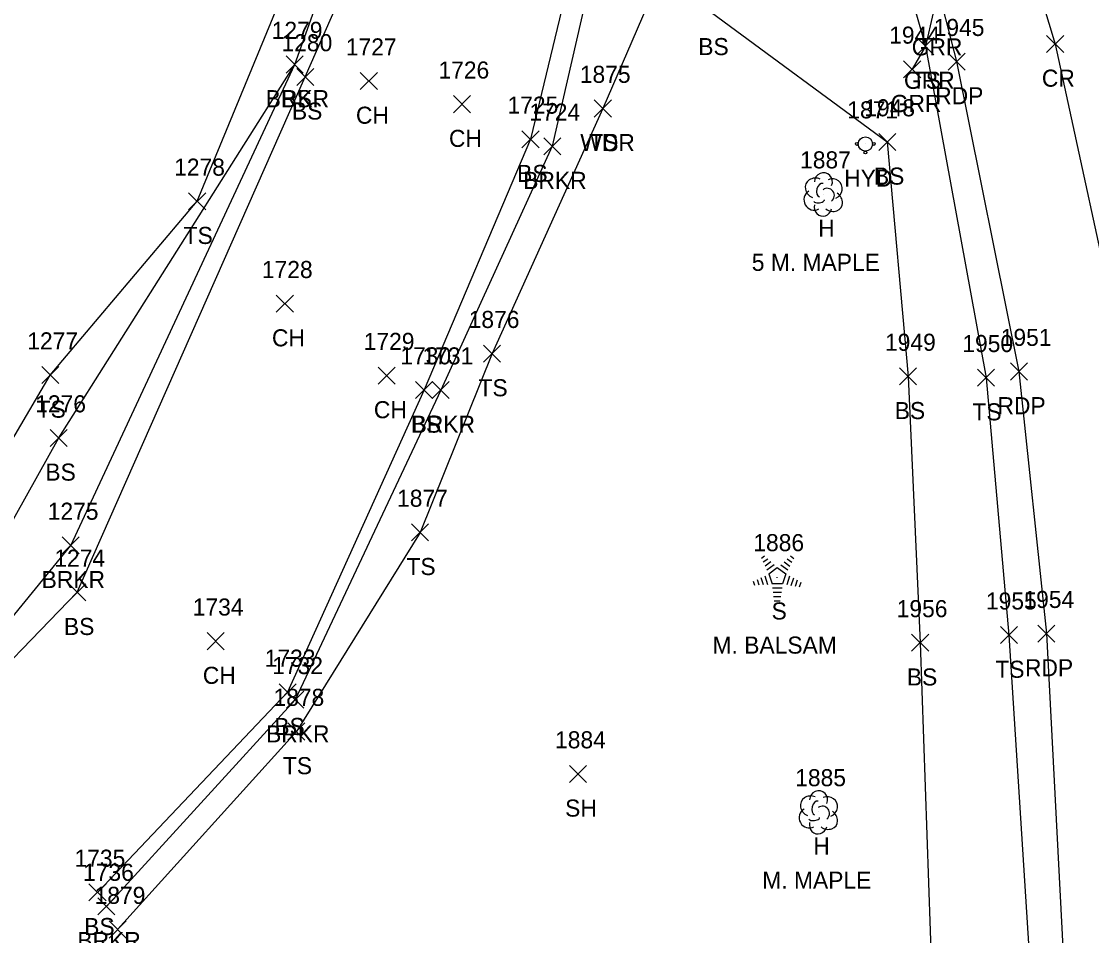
# Model space of a CAD drawing. Extents: x 1651305 to 1654558, y 539481 to 548441.
# Drawn here: x 1654251.1 to 1654376.5, y 544437.8 to 544544.9 of the extents above; entities that cross this region are included whole.
import ezdxf

# ---------------------------------------------------------------- set-up
doc = ezdxf.new("R2010")
doc.units = 0
for name, color, linetype in [('L_A', 7, 'Continuous'), ('L_C', 7, 'Continuous'), ('L_I', 7, 'Continuous'), ('L_TIC', 7, 'Continuous'), ('LAWA', 7, 'Continuous'), ('LAWE', 7, 'Continuous'), ('LELB', 7, 'Continuous'), ('LTC', 7, 'Continuous'), ('LTD', 7, 'Continuous'), ('P_A', 7, 'Continuous'), ('P_I', 7, 'Continuous'), ('P_TIC', 7, 'Continuous'), ('PET', 7, 'Continuous'), ('PRC', 7, 'Continuous'), ('R_A', 7, 'Continuous'), ('R_I', 7, 'Continuous'), ('R_TIC', 7, 'Continuous'), ('RGR', 7, 'Continuous'), ('U_A', 7, 'Continuous'), ('U_I', 7, 'Continuous'), ('UWFH', 7, 'Continuous')]:
    doc.layers.add(name, color=color, linetype=linetype)

msp = doc.modelspace()

# ---------------------------------------------------------------- linework, layer by layer
at = {"layer": 'L_TIC'}
for points in [[(1654356.01, 544541.02), (1654358.01, 544543.02)], [(1654358.01, 544541.02), (1654356.01, 544543.02)], [(1654282.12, 544538.87), (1654284.12, 544540.87)], [(1654284.12, 544538.87), (1654282.12, 544540.87)], [(1654282.12, 544538.87), (1654284.12, 544540.87)], [(1654284.12, 544538.87), (1654282.12, 544540.87)], [(1654283.35, 544537.42), (1654285.35, 544539.42)], [(1654285.35, 544537.42), (1654283.35, 544539.42)], [(1654290.8, 544536.93), (1654292.8, 544538.93)], [(1654292.8, 544536.93), (1654290.8, 544538.93)], [(1654301.71, 544534.22), (1654303.71, 544536.22)], [(1654303.71, 544534.22), (1654301.71, 544536.22)], [(1654318.22, 544533.72), (1654320.22, 544535.72)], [(1654320.22, 544533.72), (1654318.22, 544535.72)], [(1654318.22, 544533.72), (1654320.22, 544535.72)], [(1654320.22, 544533.72), (1654318.22, 544535.72)], [(1654309.74, 544530.11), (1654311.74, 544532.11)], [(1654311.74, 544530.11), (1654309.74, 544532.11)], [(1654351.54, 544529.8), (1654353.54, 544531.8)], [(1654353.54, 544529.8), (1654351.54, 544531.8)], [(1654312.3, 544529.3), (1654314.3, 544531.3)], [(1654314.3, 544529.3), (1654312.3, 544531.3)], [(1654270.69, 544522.85), (1654272.69, 544524.85)], [(1654272.69, 544522.85), (1654270.69, 544524.85)], [(1654280.96, 544510.86), (1654282.96, 544512.86)], [(1654282.96, 544510.86), (1654280.96, 544512.86)], [(1654305.24, 544505.01), (1654307.24, 544507.01)], [(1654307.24, 544505.01), (1654305.24, 544507.01)], [(1654253.47, 544502.5), (1654255.47, 544504.5)], [(1654255.47, 544502.5), (1654253.47, 544504.5)], [(1654292.9, 544502.44), (1654294.9, 544504.44)], [(1654294.9, 544502.44), (1654292.9, 544504.44)], [(1654353.98, 544502.34), (1654355.98, 544504.34)], [(1654355.98, 544502.34), (1654353.98, 544504.34)], [(1654363.12, 544502.19), (1654365.12, 544504.19)], [(1654365.12, 544502.19), (1654363.12, 544504.19)], [(1654297.27, 544500.75), (1654299.27, 544502.75)], [(1654299.27, 544500.75), (1654297.27, 544502.75)], [(1654299.22, 544500.74), (1654301.22, 544502.74)], [(1654301.22, 544500.74), (1654299.22, 544502.74)], [(1654254.46, 544495.13), (1654256.46, 544497.13)], [(1654256.46, 544495.13), (1654254.46, 544497.13)], [(1654296.8, 544484.07), (1654298.8, 544486.07)], [(1654298.8, 544484.07), (1654296.8, 544486.07)], [(1654255.87, 544482.55), (1654257.87, 544484.55)], [(1654257.87, 544482.55), (1654255.87, 544484.55)], [(1654256.64, 544477.05), (1654258.64, 544479.05)], [(1654258.64, 544477.05), (1654256.64, 544479.05)], [(1654272.86, 544471.33), (1654274.86, 544473.33)], [(1654274.86, 544471.33), (1654272.86, 544473.33)], [(1654355.4, 544471.14), (1654357.4, 544473.14)], [(1654357.4, 544471.14), (1654355.4, 544473.14)], [(1654365.8, 544472.04), (1654367.8, 544474.04)], [(1654367.8, 544472.04), (1654365.8, 544474.04)], [(1654281.29, 544465.34), (1654283.29, 544467.34)], [(1654283.29, 544465.34), (1654281.29, 544467.34)], [(1654282.17, 544464.47), (1654284.17, 544466.47)], [(1654284.17, 544464.47), (1654282.17, 544466.47)], [(1654282.32, 544460.75), (1654284.32, 544462.75)], [(1654284.32, 544460.75), (1654282.32, 544462.75)], [(1654315.31, 544455.78), (1654317.31, 544457.78)], [(1654317.31, 544455.78), (1654315.31, 544457.78)], [(1654259.01, 544441.91), (1654261.01, 544443.91)], [(1654261.01, 544441.91), (1654259.01, 544443.91)], [(1654260.06, 544440.26), (1654262.06, 544442.26)], [(1654262.06, 544440.26), (1654260.06, 544442.26)], [(1654261.37, 544437.56), (1654263.37, 544439.56)], [(1654263.37, 544437.56), (1654261.37, 544439.56)]]:
    msp.add_lwpolyline(points, dxfattribs=at)
at = {"layer": 'LAWA'}
msp.add_lwpolyline([(1654338.93, 544582.03), (1654337.56, 544570.74), (1654326.65, 544551.9), (1654319.22, 544534.72)], dxfattribs=at)
at = {"layer": 'LAWE'}
for points in [[(1654242.51, 544465.97), (1654256.87, 544483.55), (1654283.12, 544539.87), (1654291.83, 544564.24), (1654301.76, 544593.78), (1654310.98, 544627.69), (1654314.7, 544654.65), (1654333.85, 544703.3), (1654340.89, 544719.25), (1654343, 544745.95), (1654343.54, 544777), (1654341.26, 544814.62), (1654342.7, 544842.64), (1654342.65, 544866.8)], [(1654375.94, 544856.31), (1654377.08, 544805.55), (1654378.9, 544780.84), (1654375.25, 544758.97), (1654375.2, 544735.18), (1654374.98, 544710.3), (1654371.32, 544695.81), (1654368.77, 544679.57), (1654363.1, 544667.03), (1654358.05, 544658.63), (1654352.36, 544650.11), (1654344.9, 544634.32), (1654334.88, 544605.42), (1654326.4, 544588.83), (1654321.27, 544565.19), (1654313.3, 544530.3), (1654300.22, 544501.74), (1654283.17, 544465.47), (1654261.06, 544441.26)]]:
    msp.add_lwpolyline(points, dxfattribs=at)
at = {"layer": 'LELB'}
for points in [[(1654243.66, 544463.61), (1654257.64, 544478.05), (1654284.35, 544538.42), (1654294.46, 544561.39), (1654312.81, 544626.03), (1654318.85, 544643.27), (1654339.17, 544696.64), (1654344.53, 544715.65), (1654345.59, 544746.87), (1654345.75, 544776.72), (1654344.63, 544815.2), (1654344.44, 544841.84), (1654343.53, 544866.97)], [(1654374.34, 544855.82), (1654375.22, 544803.45), (1654375.07, 544780.81), (1654373.47, 544758.47), (1654373.91, 544734.87), (1654373.92, 544712.91), (1654369.62, 544696.27), (1654366.92, 544680.67), (1654362.17, 544668.56), (1654357.64, 544659.43), (1654350.7, 544650.57), (1654343.25, 544636.93), (1654333.62, 544607.27), (1654325.31, 544589.17), (1654319.06, 544565.66), (1654310.74, 544531.11), (1654298.27, 544501.75), (1654282.29, 544466.34), (1654260.01, 544442.91)], [(1654236.19, 544472.4), (1654254.47, 544503.5), (1654271.69, 544523.85), (1654289.21, 544566.35), (1654298.06, 544598.76)], [(1654343.58, 544585.05), (1654350.34, 544565.29), (1654357.01, 544542.02), (1654364.12, 544503.19), (1654366.8, 544473.04), (1654369.36, 544432.64), (1654369.04, 544397.45), (1654364.12, 544367.94), (1654358.93, 544342.15)], [(1654331.96, 544545.97), (1654352.54, 544530.8), (1654354.98, 544503.34), (1654356.4, 544472.14), (1654357.75, 544432.79), (1654359.2, 544399.51), (1654355.94, 544368.56), (1654354.81, 544342.89)], [(1654240.47, 544469.32), (1654255.46, 544496.13), (1654283.12, 544539.87)], [(1654319.22, 544534.72), (1654306.24, 544506.01), (1654297.8, 544485.07), (1654283.32, 544461.75), (1654262.37, 544438.56)]]:
    msp.add_lwpolyline(points, dxfattribs=at)
at = {"layer": 'LTC'}
for p, q in [((1654337.8, 544482.07), (1654338.15, 544482.33)), ((1654338.01, 544481.61), (1654338.54, 544481.99)), ((1654338.22, 544481.14), (1654338.92, 544481.65)), ((1654340.82, 544481.97), (1654341.37, 544481.57)), ((1654341.2, 544482.31), (1654341.61, 544482.01)), ((1654338.43, 544480.68), (1654339.3, 544481.31)), ((1654338.65, 544480.22), (1654339.66, 544480.96)), ((1654339.66, 544480.96), (1654340.66, 544480.23)), ((1654340.08, 544481.27), (1654340.89, 544480.68)), ((1654340.45, 544481.62), (1654341.13, 544481.12)), ((1654336.83, 544479.35), (1654336.98, 544478.89)), ((1654337.29, 544479.57), (1654337.5, 544478.92)), ((1654337.74, 544479.79), (1654338.01, 544478.95)), ((1654338.2, 544480), (1654338.53, 544478.98)), ((1654338.65, 544480.22), (1654339.04, 544479.03)), ((1654340.66, 544480.23), (1654340.27, 544479.03)), ((1654341.1, 544479.96), (1654340.76, 544478.92)), ((1654341.54, 544479.71), (1654341.25, 544478.83)), ((1654341.99, 544479.46), (1654341.75, 544478.73)), ((1654342.43, 544479.21), (1654342.24, 544478.64)), ((1654340.27, 544479.03), (1654339.04, 544479.03)), ((1654340.23, 544478.53), (1654339.09, 544478.53)), ((1654340.15, 544478.03), (1654339.16, 544478.03)), ((1654340.06, 544477.53), (1654339.23, 544477.53)), ((1654339.98, 544477.03), (1654339.3, 544477.03))]:
    msp.add_line(p, q, dxfattribs=at)
at = {"layer": 'LTD'}
for p, q in [((1654345.02, 544524.7), (1654345.02, 544524.7)), ((1654345.02, 544524.7), (1654345.02, 544524.7)), ((1654344.45, 544452.34), (1654344.45, 544452.34)), ((1654344.45, 544452.34), (1654344.45, 544452.34))]:
    msp.add_line(p, q, dxfattribs=at)
for centre in [(1654345.07, 544526.14), (1654344.5, 544453.77)]:
    msp.add_arc(centre, 1.05, 335.5272, 180.9563, dxfattribs=at)
for centre, major_axis, ratio, start_param, end_param in [((1654344.23, 544525.37), (1.21, -0.51), 0.895232, 1.570796, 4.712389), ((1654344.81, 544525.16), (-0.208, -0.792), 0.645439, 3.141593, 6.283185), ((1654346.06, 544525.29), (-1.14, -0.48), 0.949671, 1.570796, 4.712389), ((1654343.94, 544523.99), (0.58, -1.04), 0.959034, 3.141593, 6.283185), ((1654345.52, 544524.54), (-0.5, 0.667), 0.989748, 3.141593, 6.283185), ((1654346.02, 544523.87), (-1.09, 0.79), 0.841452, 1.570796, 4.712389), ((1654345.02, 544523.2), (0.26, 1.06), 0.942809, 1.570796, 4.712389), ((1654344.56, 544523.95), (-0.625, -0.083), 0.423636, 0, 3.141593), ((1654343.66, 544453), (1.21, -0.51), 0.895232, 1.570796, 4.712389), ((1654345.49, 544452.92), (-1.14, -0.48), 0.949671, 1.570796, 4.712389), ((1654344.24, 544452.79), (-0.208, -0.792), 0.645439, 3.141593, 6.283185), ((1654344.95, 544452.17), (-0.5, 0.667), 0.989748, 3.141593, 6.283185), ((1654343.37, 544451.63), (0.58, -1.04), 0.959034, 3.141593, 6.283185), ((1654343.99, 544451.59), (-0.625, -0.083), 0.423636, 0, 3.141593), ((1654345.45, 544451.5), (-1.09, 0.79), 0.841452, 1.570796, 4.712389), ((1654344.45, 544450.84), (0.26, 1.06), 0.942809, 1.570796, 4.712389)]:
    msp.add_ellipse(centre, major_axis=major_axis, ratio=ratio, start_param=start_param, end_param=end_param, dxfattribs=at)
at = {"layer": 'P_TIC'}
for points in [[(1654371.22, 544541.27), (1654373.22, 544543.27)], [(1654373.22, 544541.27), (1654371.22, 544543.27)], [(1654359.67, 544539.21), (1654361.67, 544541.21)], [(1654361.67, 544539.21), (1654359.67, 544541.21)], [(1654366.97, 544502.91), (1654368.97, 544504.91)], [(1654368.97, 544502.91), (1654366.97, 544504.91)], [(1654370.19, 544472.22), (1654372.19, 544474.22)], [(1654372.19, 544472.22), (1654370.19, 544474.22)]]:
    msp.add_lwpolyline(points, dxfattribs=at)
at = {"layer": 'PET'}
msp.add_lwpolyline([(1654345.04, 544588.36), (1654352.84, 544566.03), (1654357.71, 544551.64), (1654360.67, 544540.21), (1654367.97, 544503.91), (1654371.19, 544473.22), (1654373.31, 544432.69), (1654372.37, 544396.63), (1654369.95, 544367.4), (1654366.85, 544341.54), (1654364.49, 544322.02), (1654359.18, 544276.5), (1654356.39, 544249.38), (1654353.63, 544216.56), (1654349.27, 544178.19), (1654347.29, 544164.71), (1654345.69, 544149.48), (1654340.92, 544117.48), (1654336.05, 544077.13)], dxfattribs=at)
at = {"layer": 'PRC'}
msp.add_lwpolyline([(1654350.59, 544607.19), (1654355.93, 544592.7), (1654363.68, 544570.63), (1654372.22, 544542.27), (1654380.24, 544505.39), (1654384.95, 544473.92), (1654386.82, 544433.75), (1654385.71, 544395.52), (1654383.86, 544366), (1654380.92, 544339.65), (1654378, 544311.09), (1654373.89, 544274.84), (1654369.01, 544231.01), (1654366.63, 544212.46), (1654362.44, 544177.97), (1654359.49, 544151.89), (1654354.07, 544107.93), (1654348.42, 544063.01)], dxfattribs=at)
at = {"layer": 'R_TIC'}
for points in [[(1654356.01, 544541.02), (1654358.01, 544543.02)], [(1654358.01, 544541.02), (1654356.01, 544543.02)], [(1654354.46, 544538.31), (1654356.46, 544540.31)], [(1654356.46, 544538.31), (1654354.46, 544540.31)]]:
    msp.add_lwpolyline(points, dxfattribs=at)
at = {"layer": 'RGR'}
msp.add_lwpolyline([(1654344.61, 544587.06), (1654352.32, 544566.01), (1654357.15, 544551.7), (1654357.92, 544545.93), (1654357.01, 544542.02), (1654355.46, 544539.31)], dxfattribs=at)
at = {"layer": 'UWFH'}
msp.add_line((1654349.98, 544530.56), (1654349.98, 544530.56), dxfattribs=at)
for centre, radius in [((1654348.98, 544530.56), 0.167), ((1654349.98, 544530.56), 0.833), ((1654350.98, 544530.56), 0.167), ((1654349.98, 544529.56), 0.167)]:
    msp.add_circle(centre, radius, dxfattribs=at)

# ---------------------------------------------------------------- texts
at = {"layer": 'L_A'}
for s, p in [('BS', (1654330.4, 544540.97)), ('TS', (1654355.42, 544537.02)), ('BRKR', (1654279.71, 544534.87)), ('BS', (1654281.56, 544534.87)), ('BS', (1654282.79, 544533.42)), ('CH', (1654290.29, 544532.93)), ('CH', (1654301.19, 544530.22)), ('WDR', (1654316.58, 544529.72)), ('TS', (1654317.63, 544529.72)), ('BS', (1654309.18, 544526.11)), ('BRKR', (1654309.89, 544525.3)), ('BS', (1654350.98, 544525.8)), ('TS', (1654270.1, 544518.85)), ('H', (1654344.45, 544519.7)), ('CH', (1654280.45, 544506.86)), ('TS', (1654304.65, 544501.01)), ('TS', (1654252.88, 544498.5)), ('CH', (1654292.39, 544498.44)), ('BS', (1654353.42, 544498.34)), ('TS', (1654362.52, 544498.19)), ('BS', (1654296.71, 544496.75)), ('BRKR', (1654296.81, 544496.74)), ('BS', (1654253.9, 544491.13)), ('TS', (1654296.21, 544480.07)), ('BRKR', (1654253.46, 544478.55)), ('S', (1654338.99, 544474.87)), ('BS', (1654256.08, 544473.05)), ('CH', (1654272.35, 544467.33)), ('BS', (1654354.84, 544467.14)), ('TS', (1654365.21, 544468.04)), ('BS', (1654280.73, 544461.34)), ('BRKR', (1654279.76, 544460.47)), ('TS', (1654281.73, 544456.75)), ('SH', (1654314.8, 544451.78)), ('H', (1654343.88, 544447.34)), ('BS', (1654258.45, 544437.91)), ('BRKR', (1654257.65, 544436.26))]:
    msp.add_text(s, height=2, dxfattribs=at).set_placement(p)
at = {"layer": 'L_C'}
for s, p in [('5 M. MAPLE', (1654336.67, 544515.7)), ('M. BALSAM', (1654332.07, 544470.87)), ('M. MAPLE', (1654337.9, 544443.34))]:
    msp.add_text(s, height=2, dxfattribs=at).set_placement(p)
at = {"layer": 'L_I'}
for s, p in [('1279', (1654280.42, 544542.87)), ('1279', (1654280.42, 544542.87)), ('1280', (1654281.57, 544541.42)), ('1727', (1654289.11, 544540.93)), ('1726', (1654299.96, 544538.22)), ('1875', (1654316.52, 544537.72)), ('1875', (1654316.52, 544537.72)), ('1725', (1654308.05, 544534.11)), ('1948', (1654349.85, 544533.8)), ('1724', (1654310.61, 544533.3)), ('1887', (1654342.33, 544527.7)), ('1278', (1654268.99, 544526.85)), ('1728', (1654279.27, 544514.86)), ('1876', (1654303.5, 544509.01)), ('1277', (1654251.78, 544506.5)), ('1729', (1654291.2, 544506.44)), ('1949', (1654352.28, 544506.34)), ('1950', (1654361.34, 544506.19)), ('1730', (1654295.49, 544504.75)), ('1731', (1654298.09, 544504.74)), ('1276', (1654252.71, 544499.13)), ('1877', (1654295.11, 544488.07)), ('1275', (1654254.18, 544486.55)), ('1886', (1654336.85, 544482.87)), ('1274', (1654254.95, 544481.05)), ('1955', (1654364.11, 544476.04)), ('1734', (1654271.17, 544475.33)), ('1956', (1654353.65, 544475.14)), ('1733', (1654279.6, 544469.34)), ('1732', (1654280.48, 544468.47)), ('1878', (1654280.63, 544464.75)), ('1884', (1654313.62, 544459.78)), ('1885', (1654341.76, 544455.34)), ('1735', (1654257.32, 544445.91)), ('1736', (1654258.32, 544444.26)), ('1879', (1654259.67, 544441.56))]:
    msp.add_text(s, height=2, dxfattribs=at).set_placement(p)
at = {"layer": 'LTC'}
msp.add_text('.', height=1.04, rotation=270, dxfattribs=at).set_placement((1654339.54, 544479.97))
at = {"layer": 'P_A'}
for s, p in [('CR', (1654370.66, 544537.27)), ('RDP', (1654358.16, 544535.21)), ('RDP', (1654365.46, 544498.91)), ('RDP', (1654368.68, 544468.22))]:
    msp.add_text(s, height=2, dxfattribs=at).set_placement(p)
at = {"layer": 'P_I'}
for s, p in [('1945', (1654357.98, 544543.21)), ('1951', (1654365.84, 544506.91)), ('1954', (1654368.5, 544476.22))]:
    msp.add_text(s, height=2, dxfattribs=at).set_placement(p)
at = {"layer": 'R_A'}
for p in [(1654355.41, 544540.93), (1654354.5, 544537.02), (1654352.95, 544534.31)]:
    msp.add_text('GRR', height=2, dxfattribs=at).set_placement(p)
at = {"layer": 'R_I'}
msp.add_text('1944', height=2, dxfattribs=at).set_placement((1654352.77, 544542.31))
at = {"layer": 'U_A'}
msp.add_text('HYD', height=2, dxfattribs=at).set_placement((1654347.5, 544525.56))
at = {"layer": 'U_I'}
msp.add_text('1871', height=2, dxfattribs=at).set_placement((1654347.86, 544533.56))

doc.saveas('drawing.dxf')
